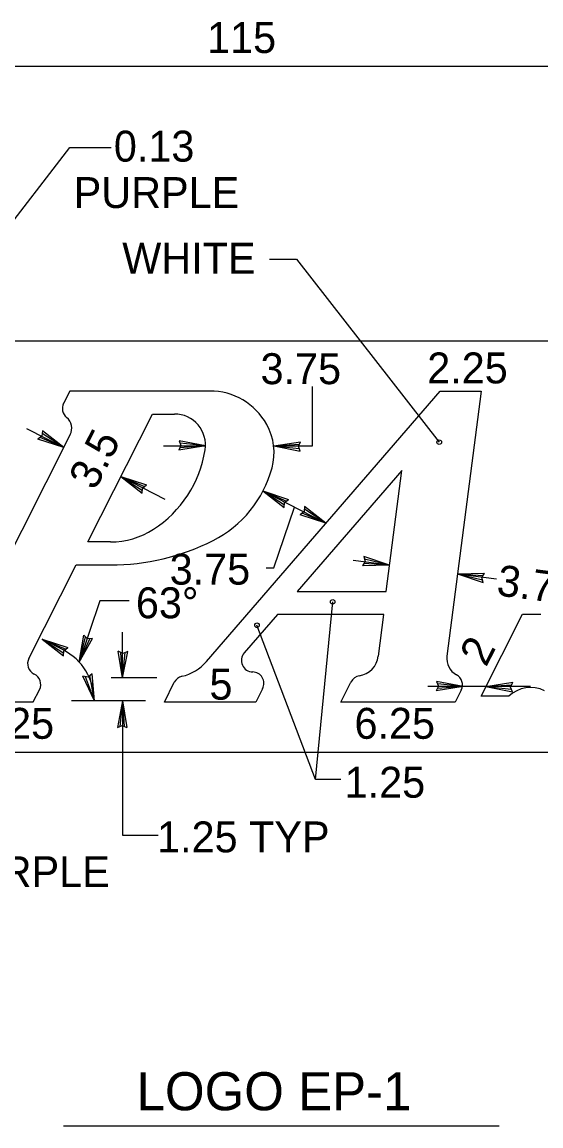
# Model space of a CAD drawing. Extents: x 10268197 to 10269179, y 2141503 to 2142677.
# Drawn here: x 10268484.88 to 10268496.62, y 2142146.95 to 2142171.93 of the extents above; entities that cross this region are included whole.
import ezdxf

# ---------------------------------------------------------------- set-up
doc = ezdxf.new("R2010")
doc.units = 0
for name, color, linetype in [('1', 7, 'Continuous'), ('2', 7, 'Continuous'), ('21', 7, 'Continuous')]:
    doc.layers.add(name, color=color, linetype=linetype)

msp = doc.modelspace()

# ---------------------------------------------------------------- linework, layer by layer
at = {"layer": '1'}
for p, q in [((10268466.124, 2142170.939), (10268491.278, 2142170.939)), ((10268491.278, 2142170.939), (10268513.738, 2142170.939)), ((10268483.936, 2142166.474), (10268485.961, 2142169.092)), ((10268485.961, 2142169.092), (10268486.898, 2142169.092)), ((10268490.475, 2142166.565), (10268491.091, 2142166.565)), ((10268491.091, 2142166.565), (10268494.319, 2142162.425)), ((10268491.453, 2142162.34), (10268491.453, 2142163.685)), ((10268484.976, 2142162.734), (10268485.821, 2142162.302)), ((10268485.338, 2142162.68), (10268485.329, 2142162.564)), ((10268485.821, 2142162.302), (10268485.333, 2142162.619)), ((10268485.821, 2142162.302), (10268485.338, 2142162.68)), ((10268485.329, 2142162.564), (10268485.239, 2142162.491)), ((10268485.821, 2142162.302), (10268485.239, 2142162.491)), ((10268485.821, 2142162.302), (10268485.286, 2142162.53)), ((10268488.475, 2142162.35), (10268488.427, 2142162.244)), ((10268489.033, 2142162.34), (10268488.431, 2142162.457)), ((10268488.431, 2142162.457), (10268488.475, 2142162.35)), ((10268489.033, 2142162.34), (10268488.454, 2142162.401)), ((10268490.573, 2142162.34), (10268491.179, 2142162.436)), ((10268490.573, 2142162.34), (10268491.153, 2142162.381)), ((10268491.131, 2142162.331), (10268491.179, 2142162.436)), ((10268488.082, 2142162.34), (10268489.033, 2142162.34)), ((10268489.033, 2142162.34), (10268488.427, 2142162.244)), ((10268489.033, 2142162.34), (10268488.452, 2142162.3)), ((10268490.573, 2142162.34), (10268491.453, 2142162.34)), ((10268490.573, 2142162.34), (10268491.175, 2142162.224)), ((10268490.573, 2142162.34), (10268491.152, 2142162.28)), ((10268491.175, 2142162.224), (10268491.131, 2142162.331)), ((10268487.115, 2142161.645), (10268488.112, 2142161.137)), ((10268487.115, 2142161.645), (10268487.698, 2142161.456)), ((10268487.115, 2142161.645), (10268487.598, 2142161.267)), ((10268487.115, 2142161.645), (10268487.603, 2142161.329)), ((10268487.115, 2142161.645), (10268487.65, 2142161.418)), ((10268487.598, 2142161.267), (10268487.607, 2142161.384)), ((10268487.607, 2142161.384), (10268487.698, 2142161.456)), ((10268490.328, 2142161.32), (10268491.756, 2142160.593)), ((10268490.328, 2142161.32), (10268490.911, 2142161.131)), ((10268490.328, 2142161.32), (10268490.812, 2142160.943)), ((10268490.328, 2142161.32), (10268490.816, 2142161.004)), ((10268490.328, 2142161.32), (10268490.863, 2142161.093)), ((10268490.82, 2142161.059), (10268490.911, 2142161.131)), ((10268490.812, 2142160.943), (10268490.82, 2142161.059)), ((10268493.193, 2142159.642), (10268492.371, 2142159.75)), ((10268492.641, 2142159.724), (10268492.58, 2142159.626)), ((10268493.193, 2142159.642), (10268492.58, 2142159.626)), ((10268493.193, 2142159.642), (10268492.611, 2142159.836)), ((10268492.611, 2142159.836), (10268492.641, 2142159.724)), ((10268493.193, 2142159.642), (10268492.613, 2142159.677)), ((10268493.193, 2142159.642), (10268492.627, 2142159.777)), ((10268494.733, 2142159.443), (10268495.346, 2142159.46)), ((10268494.733, 2142159.443), (10268495.611, 2142159.329)), ((10268494.733, 2142159.443), (10268495.314, 2142159.25)), ((10268494.733, 2142159.443), (10268495.299, 2142159.31)), ((10268494.733, 2142159.443), (10268495.313, 2142159.409)), ((10268495.284, 2142159.362), (10268495.346, 2142159.46)), ((10268495.314, 2142159.25), (10268495.284, 2142159.362)), ((10268486.64, 2142158.833), (10268486.171, 2142157.449)), ((10268487.305, 2142158.833), (10268486.64, 2142158.833)), ((10268491.522, 2142154.792), (10268491.908, 2142158.81)), ((10268487.152, 2142157.087), (10268487.152, 2142158.122)), ((10268491.522, 2142154.792), (10268490.194, 2142158.281)), ((10268485.809, 2142157.722), (10268485.333, 2142157.965)), ((10268485.333, 2142157.965), (10268485.916, 2142157.775)), ((10268485.333, 2142157.965), (10268485.816, 2142157.587)), ((10268485.333, 2142157.965), (10268485.821, 2142157.648)), ((10268485.333, 2142157.965), (10268485.868, 2142157.738)), ((10268486.171, 2142157.449), (10268486.274, 2142158.053)), ((10268486.171, 2142157.449), (10268486.318, 2142158.011)), ((10268486.171, 2142157.449), (10268486.474, 2142157.981)), ((10268486.171, 2142157.449), (10268486.414, 2142157.977)), ((10268486.359, 2142157.974), (10268486.274, 2142158.053)), ((10268486.474, 2142157.981), (10268486.359, 2142157.974)), ((10268485.816, 2142157.587), (10268485.826, 2142157.703)), ((10268485.826, 2142157.703), (10268485.916, 2142157.775)), ((10268487.152, 2142157.087), (10268487.056, 2142157.693)), ((10268487.162, 2142157.644), (10268487.056, 2142157.693)), ((10268487.152, 2142157.087), (10268487.112, 2142157.667)), ((10268487.152, 2142157.087), (10268487.269, 2142157.688)), ((10268487.152, 2142157.087), (10268487.213, 2142157.666)), ((10268487.269, 2142157.688), (10268487.162, 2142157.644)), ((10268486.515, 2142156.569), (10268486.257, 2142157.125)), ((10268486.371, 2142157.108), (10268486.257, 2142157.125)), ((10268486.515, 2142156.569), (10268486.317, 2142157.116)), ((10268486.462, 2142157.18), (10268486.371, 2142157.108)), ((10268486.515, 2142156.569), (10268486.414, 2142157.142)), ((10268486.515, 2142156.569), (10268486.462, 2142157.18)), ((10268487.929, 2142157.087), (10268486.894, 2142157.087)), ((10268494.857, 2142156.892), (10268494.06, 2142156.892)), ((10268495.374, 2142156.892), (10268494.857, 2142156.892)), ((10268496.384, 2142156.892), (10268495.374, 2142156.892)), ((10268487.67, 2142156.569), (10268485.998, 2142156.569)), ((10268487.152, 2142156.569), (10268487.035, 2142155.968)), ((10268487.152, 2142156.569), (10268487.092, 2142155.991)), ((10268487.152, 2142156.569), (10268487.152, 2142153.533)), ((10268487.152, 2142156.569), (10268487.249, 2142155.964)), ((10268487.152, 2142156.569), (10268487.193, 2142155.99)), ((10268487.035, 2142155.968), (10268487.143, 2142156.012)), ((10268487.143, 2142156.012), (10268487.249, 2142155.964)), ((10268492.094, 2142154.792), (10268491.522, 2142154.792)), ((10268487.152, 2142153.533), (10268487.96, 2142153.533))]:
    msp.add_line(p, q, dxfattribs=at)
msp.add_lwpolyline([(10268490.404, 2142159.581), (10268490.579, 2142159.581), (10268491.042, 2142160.957)], dxfattribs=at)
for centre in [(10268494.319, 2142162.425), (10268491.908, 2142158.81), (10268490.194, 2142158.281)]:
    msp.add_circle(centre, 0.0518, dxfattribs=at)
msp.add_arc((10268485.221, 2142156.57), 1.294, 0, 62.9941, dxfattribs=at)
at = {"layer": '2'}
for p, q in [((10268484.215, 2142164.721), (10268513.738, 2142164.721)), ((10268485.961, 2142163.583), (10268485.82, 2142163.304)), ((10268489.131, 2142163.583), (10268485.961, 2142163.583)), ((10268489.051, 2142157.458), (10268494.336, 2142163.583)), ((10268494.336, 2142163.583), (10268495.267, 2142163.583)), ((10268495.267, 2142163.583), (10268494.493, 2142157.582)), ((10268486.367, 2142160.167), (10268487.832, 2142163.061)), ((10268487.832, 2142163.061), (10268488.33, 2142163.061)), ((10268485.97, 2142162.597), (10268483.408, 2142157.53)), ((10268493.47, 2142161.784), (10268491.107, 2142159.046)), ((10268493.116, 2142159.046), (10268493.47, 2142161.784)), ((10268486.88, 2142160.167), (10268486.367, 2142160.167)), ((10268485.033, 2142157.531), (10268486.104, 2142159.646)), ((10268486.104, 2142159.646), (10268486.88, 2142159.646)), ((10268491.107, 2142159.046), (10268493.116, 2142159.046)), ((10268490.659, 2142158.525), (10268489.908, 2142157.655)), ((10268493.063, 2142158.525), (10268490.659, 2142158.525)), ((10268492.941, 2142157.582), (10268493.063, 2142158.525)), ((10268495.264, 2142156.674), (10268496.204, 2142158.533)), ((10268496.204, 2142158.533), (10268496.619, 2142158.533)), ((10268488.099, 2142156.543), (10268488.324, 2142156.989)), ((10268492.093, 2142156.543), (10268492.321, 2142156.996)), ((10268485.133, 2142156.544), (10268485.274, 2142156.822)), ((10268490.322, 2142156.845), (10268490.169, 2142156.543)), ((10268494.817, 2142156.813), (10268494.681, 2142156.543)), ((10268495.893, 2142156.674), (10268495.264, 2142156.674)), ((10268482.545, 2142156.544), (10268485.133, 2142156.544)), ((10268490.169, 2142156.543), (10268488.099, 2142156.543)), ((10268494.681, 2142156.543), (10268492.093, 2142156.543)), ((10268483.351, 2142155.405), (10268508.992, 2142155.405))]:
    msp.add_line(p, q, dxfattribs=at)
for centre, major_axis, start_param, end_param in [((10268489.13, 2142162.097), (0, 1.486), 5.226065, 6.283185), ((10268486.05, 2142163.186), (0, -0.261), 4.240773, 5.605302), ((10268485.693, 2142162.739), (0, -0.313), 1.099604, 2.46371), ((10268488.33, 2142162.358), (0, -0.704), 1.415043, 3.141593), ((10268489.288, 2142162.186), (0, 1.303), 4.445482, 5.226065), ((10268486.463, 2142162.653), (0, -2.607), 0.565847, 1.415043), ((10268488.04, 2142162.53), (0, -2.607), 0.465011, 1.30389), ((10268486.88, 2142161.993), (0, -1.825), 0, 0.565847), ((10268486.88, 2142164.86), (0, -5.214), 0, 0.465011), ((10268490.103, 2142157.485), (0, 0.261), 0.854904, 3.118676), ((10268485.264, 2142157.413), (0, 0.261), 1.099355, 2.701477), ((10268488.27, 2142158.143), (0, -1.043), 0.22194, 0.855152), ((10268492.427, 2142157.65), (0, -0.521), 0.161263, 1.440999), ((10268494.903, 2142157.529), (0, 0.417), 1.441439, 2.650585), ((10268485.043, 2142156.941), (0, 0.261), 4.241567, 5.84307), ((10268488.555, 2142156.872), (0, -0.261), 3.363532, 4.241567), ((10268490.091, 2142156.964), (0, 0.261), 4.240773, 6.260268), ((10268492.552, 2142156.878), (0, -0.261), 3.302856, 4.241567), ((10268494.586, 2142156.931), (0, 0.261), 4.240773, 5.792177), ((10268496.389, 2142156.142), (0, -0.73), 2.69443, 3.895387)]:
    msp.add_ellipse(centre, major_axis=major_axis, ratio=0.992614, start_param=start_param, end_param=end_param, dxfattribs=at)
at = {"layer": '21'}
for p, q in [((10268491.263, 2142160.855), (10268491.172, 2142160.782)), ((10268491.272, 2142160.971), (10268491.263, 2142160.855)), ((10268491.756, 2142160.593), (10268491.267, 2142160.91)), ((10268491.756, 2142160.593), (10268491.272, 2142160.971)), ((10268491.756, 2142160.593), (10268491.172, 2142160.782)), ((10268491.756, 2142160.593), (10268491.22, 2142160.82)), ((10268494.299, 2142156.902), (10268494.251, 2142156.796)), ((10268494.857, 2142156.892), (10268494.251, 2142156.796)), ((10268494.857, 2142156.892), (10268494.254, 2142157.009)), ((10268494.254, 2142157.009), (10268494.299, 2142156.902)), ((10268494.857, 2142156.892), (10268494.277, 2142156.953)), ((10268494.857, 2142156.892), (10268494.277, 2142156.852)), ((10268495.374, 2142156.892), (10268495.981, 2142156.989)), ((10268495.374, 2142156.892), (10268495.955, 2142156.933)), ((10268495.374, 2142156.892), (10268495.977, 2142156.776)), ((10268495.374, 2142156.892), (10268495.954, 2142156.832)), ((10268495.933, 2142156.883), (10268495.981, 2142156.989)), ((10268495.977, 2142156.776), (10268495.933, 2142156.883)), ((10268485.815, 2142146.948), (10268495.677, 2142146.948))]:
    msp.add_line(p, q, dxfattribs=at)

# ---------------------------------------------------------------- texts
at = {"layer": '1'}
for s, height, p in [('115', 0.7, (10268489.065, 2142171.234)), ('0.13', 0.7, (10268486.956, 2142168.775)), ('PURPLE', 0.7, (10268486.047, 2142167.725)), ('WHITE', 0.7, (10268487.146, 2142166.238)), ('3.75', 0.7, (10268490.275, 2142163.738)), ('2.25', 0.7, (10268494.047, 2142163.755)), ('63°', 0.7, (10268487.455, 2142158.439)), ('5', 0.7, (10268489.119, 2142156.596)), ('6.25', 0.7, (10268483.782, 2142155.711)), ('6.25', 0.7, (10268492.401, 2142155.711)), ('1.25', 0.7, (10268492.178, 2142154.377)), ('1.25 TYP', 0.7, (10268487.934, 2142153.14)), ('PURPLE', 0.7, (10268483.118, 2142152.353)), ('LOGO EP-1', 0.8624, (10268487.471, 2142147.302))]:
    msp.add_text(s, height=height, dxfattribs=at).set_placement(p)
for s, rotation, p in [('3.5', 62.9907, (10268486.531, 2142161.311)), ('3.75', 360, (10268488.219, 2142159.201)), ('3.75', 352.5994, (10268495.597, 2142158.961)), ('2', 63, (10268495.377, 2142157.315))]:
    msp.add_text(s, height=0.7, rotation=rotation, dxfattribs=at).set_placement(p)

doc.saveas('drawing.dxf')
